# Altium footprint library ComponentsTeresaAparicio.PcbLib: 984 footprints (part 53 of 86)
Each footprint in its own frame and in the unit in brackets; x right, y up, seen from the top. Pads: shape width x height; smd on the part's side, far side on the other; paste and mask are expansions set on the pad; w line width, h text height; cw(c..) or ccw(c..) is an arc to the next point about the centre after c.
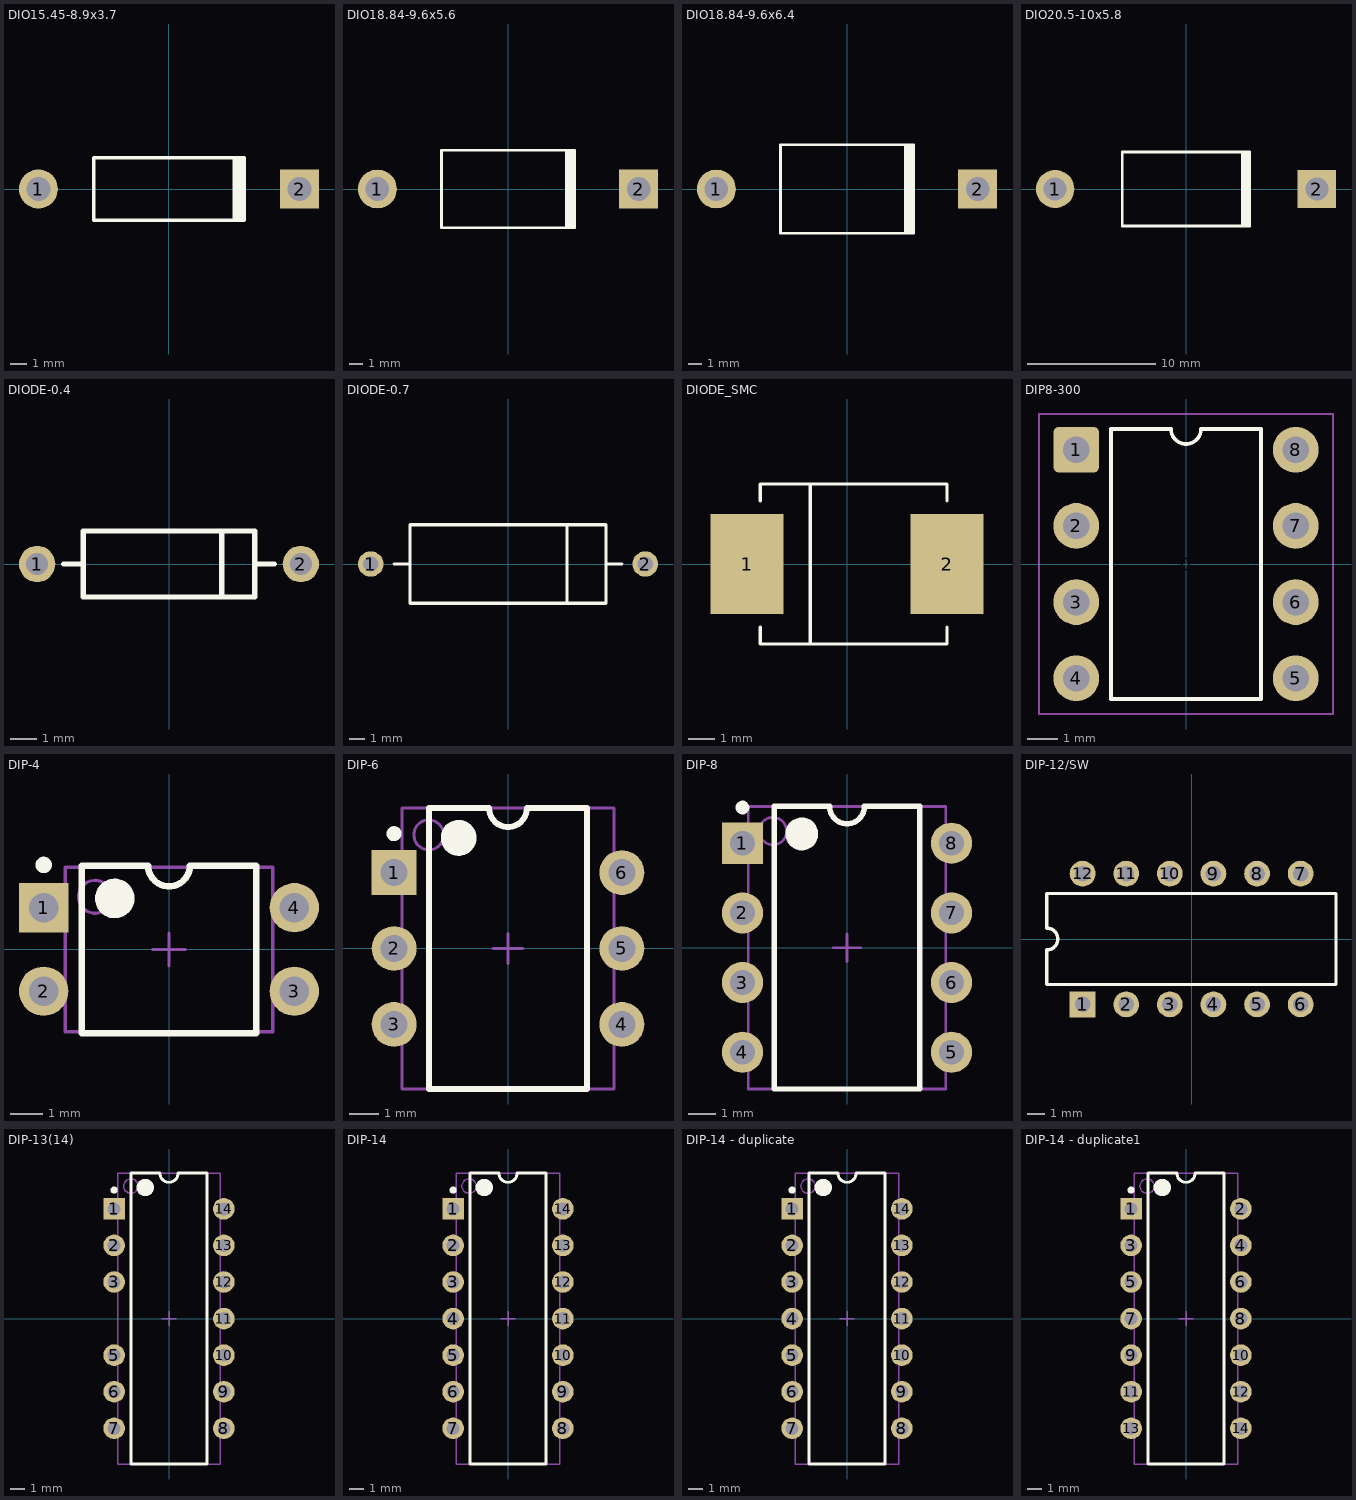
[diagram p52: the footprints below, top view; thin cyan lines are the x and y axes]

## DIO15.45-8.9x3.7 [mm] "Diode, Axial; Body 8.9 x 3.7 mm (LxDia. max), Lead Dia. 1.09 mm (max)"
height 3.7
pads (2):
  round 2.3 hole 1.4: 1(-7.725,0)
  rect 2.3x2.3 hole 1.4: 2(7.725,0)
Top Overlay:
  rectangle: 3.75,-1.85 4.55,1.85
  lines w0.2: 4.45,-1.85 -4.45,-1.85 -4.45,1.85 4.45,1.85

## DIO18.84-9.6x5.6 [mm] "Diode, Axial; Body 9.5 x 5.6 mm (LxDia. max), Lead Dia. 1.32 mm (max)"
height 5.6
pads (2):
  round 2.8 hole 1.7: 1(-9.42,0)
  rect 2.8x2.8 hole 1.7: 2(9.42,0)
Top Overlay:
  rectangle: 4.1,-2.8 4.9,2.8
  lines w0.2: 4.8,-2.8 -4.8,-2.8 -4.8,2.8 4.8,2.8

## DIO18.84-9.6x6.4 [mm] "Diode, Axial; Body 9.5 x 6.4 mm (LxDia. max), Lead Dia. 1.32 mm (max)"
height 6.4
pads (2):
  round 2.8 hole 1.7: 1(-9.42,0)
  rect 2.8x2.8 hole 1.7: 2(9.42,0)
Top Overlay:
  rectangle: 4.1,-3.2 4.9,3.2
  lines w0.2: 4.8,-3.2 -4.8,-3.2 -4.8,3.2 4.8,3.2

## DIO20.5-10x5.8 [mm] "Diode, Axial; Body 9.9 x 5.8 mm (LxDia. max), Lead Dia. 1.5 mm (max)"
height 5.8
pads (2):
  round 3 hole 1.8: 1(-10.25,0)
  rect 3x3 hole 1.8: 2(10.25,0)
Top Overlay:
  rectangle: 4.3,-2.9 5.1,2.9
  lines w0.2: 5,-2.9 -5,-2.9 -5,2.9 5,2.9

## DIODE-0.4 [mm] "Diode, Thru-Hole; 2 Leads; 0.4 in Pin Spacing"
height 2.54
pads (2):
  round 1.4 hole 0.85: 1(-5.08,0) 2(5.08,0)
Top Overlay:
  lines w0.2: -4.064,0 -3.302,0 ; 2.032,-1.27 2.032,1.27 ; 3.302,0 4.064,0 ; -3.302,-1.27 -3.302,1.27 3.302,1.27 3.302,-1.27 -3.302,-1.27

## DIODE-0.7 [mm] "Diode, Thru-Hole; 2 Leads; 0.7 in Pin Spacing"
height 5.08
pads (2):
  round 1.65 hole 1: 1(-8.89,0) 2(8.89,0)
Top Overlay:
  lines w0.2: -7.366,0 -6.35,0 ; 3.81,-2.54 3.81,2.54 ; 6.35,0 7.366,0 ; -6.35,-2.54 -6.35,2.54 6.35,2.54 6.35,-2.54 -6.35,-2.54

## DIODE_SMC [mil] "Diode; 2 Leads"
pads (2):
  rect 110x150 smd: 1(-150,0) 2(150,0)
Top Overlay:
  lines w5: -130,-95 -130,-120 150,-120 150,-95 ; -130,95 -130,120 150,120 150,95 ; -55,-120 -55,120
Mechanical 1:
  lines w1: -130,-120 150,-120 ; -130,120 150,120

## DIP8-300 [mil] "DIP, 8-Leads, 0.300\" lead span , 0.100\" lead pitch, IPC Density A"
height 210
pads (9):
  round 39.37 on Mech14: 0(0,0)
  rrect25% 60x60 hole 35: 1(-144,150)
  round 60 hole 35: 2(-144,50) 3(-144,-50) 4(-144,-150) 5(144,-150) 6(144,-50) 7(144,50) 8(144,150)
Top Overlay:
  lines w5: -98.43,-177.17 98.43,-177.17 98.43,177.17 19.69,177.17 cw(c0,177.17) -19.69,177.17 -98.43,177.17 -98.43,-177.17
Mechanical 13:
  lines w3: -98.43,-177.17 -98.43,177.17 -19.69,177.17 ccw(c0,177.17) 19.69,177.17 98.43,177.17 98.43,-177.17 -98.43,-177.17
Mechanical 14:
  lines w3: -192.91,-196.85 192.91,-196.85 192.91,196.85 -192.91,196.85 -192.91,-196.85
3D body: height 165, standoff -105, extent -149,-225 161,225

## DIP-4 [mm] "DIP; 4 Leads; Row Spacing 7.62 mm; Pitch 2.54 mm"
height 5.6
pads (4):
  rect 1.5x1.5 hole 0.9: 1(-3.81,1.27)
  round 1.5 hole 0.9: 2(-3.81,-1.27) 3(3.81,-1.27) 4(3.81,1.27)
Top Overlay:
  circle w0.25: c-3.81,2.57 r0.125
  circle w0.6: c-1.65,1.55 r0.3
  lines w0.2: -2.65,-2.55 -2.65,2.55 -0.635,2.55 ccw(c0,2.55) 0.635,2.55 2.65,2.55 2.65,-2.55 -2.65,-2.55
Mechanical 13:
  circle w0.1: c-2.25,1.6 r0.5
  lines w0.1: -3.15,-2.5 -3.15,2.5 3.15,2.5 3.15,-2.5 -3.15,-2.5
Mechanical 15:
  lines w0.1: -0.5,0 0.5,0 ; 0,-0.5 0,0.5
3D body: height 5.6, standoff 0, extent -3.15,-2.5 3.15,2.5

## DIP-6 [mm] "DIP; 6 Leads; Row Spacing 7.62 mm; Pitch 2.54 mm"
height 5.46
pads (6):
  rect 1.5x1.5 hole 0.9: 1(-3.81,2.54)
  round 1.5 hole 0.9: 2(-3.81,0) 3(-3.81,-2.54) 4(3.81,-2.54) 5(3.81,0) 6(3.81,2.54)
Top Overlay:
  circle w0.25: c-3.81,3.84 r0.125
  circle w0.6: c-1.65,3.7 r0.3
  lines w0.2: -2.65,-4.7 -2.65,4.7 -0.635,4.7 ccw(c0,4.7) 0.635,4.7 2.65,4.7 2.65,-4.7 -2.65,-4.7
Mechanical 13:
  circle w0.1: c-2.65,3.8 r0.5
  lines w0.1: -3.55,-4.7 -3.55,4.7 3.55,4.7 3.55,-4.7 -3.55,-4.7
Mechanical 15:
  lines w0.1: -0.5,0 0.5,0 ; 0,-0.5 0,0.5
3D body: height 5.46, standoff 0, extent -3.55,-4.7 3.55,4.7

## DIP-8 [mm] "DIP; 8 Leads; Row Spacing 7.62 mm; Pitch 2.54 mm"
height 5.08
pads (8):
  rect 1.5x1.5 hole 0.9: 1(-3.81,3.81)
  round 1.5 hole 0.9: 2(-3.81,1.27) 3(-3.81,-1.27) 4(-3.81,-3.81) 5(3.81,-3.81) 6(3.81,-1.27) 7(3.81,1.27) 8(3.81,3.81)
Top Overlay:
  circle w0.6: c-1.65,4.15 r0.3
  circle w0.25: c-3.81,5.11 r0.125
  lines w0.2: -2.65,-5.15 2.65,-5.15 2.65,5.15 0.635,5.15 cw(c0,5.15) -0.635,5.15 -2.65,5.15 -2.65,-5.15
Mechanical 13:
  circle w0.1: c-2.7,4.25 r0.5
  lines w0.1: -3.6,-5.15 3.6,-5.15 3.6,5.15 -3.6,5.15 -3.6,-5.15
Mechanical 15:
  lines w0.1: -0.5,0 0.5,0 ; 0,-0.5 0,0.5
3D body: height 5.08, standoff 0, extent -3.6,-5.15 3.6,5.15

## DIP-12/SW [mm] "DIP Switch; 12 Leads"
height 5.8
pads (12):
  rect 1.5x1.5 hole 0.9: 1(-6.35,-3.81)
  round 1.5 hole 0.9: 2(-3.81,-3.81) 3(-1.27,-3.81) 4(1.27,-3.81) 5(3.81,-3.81) 6(6.35,-3.81) 7(6.35,3.81) 8(3.81,3.81) 9(1.27,3.81) 10(-1.27,3.81) 11(-3.81,3.81) 12(-6.35,3.81)
Top Overlay:
  lines w0.2: -8.43,-2.65 8.41,-2.65 8.41,2.65 -8.43,2.65 -8.43,0.635 cw(c-8.43,0) -8.43,-0.635 -8.43,-2.65

## DIP-13(14) [mm] "DIP; 14 Leads (1 Absent); Row Spacing 7.62 mm; Pitch 2.54 mm"
height 5.33
pads (13):
  rect 1.5x1.5 hole 0.9: 1(-3.81,7.62)
  round 1.5 hole 0.9: 2(-3.81,5.08) 3(-3.81,2.54) 5(-3.81,-2.54) 6(-3.81,-5.08) 7(-3.81,-7.62) 8(3.81,-7.62) 9(3.81,-5.08) 10(3.81,-2.54) 11(3.81,0) 12(3.81,2.54) 13(3.81,5.08) 14(3.81,7.62)
Top Overlay:
  circle w0.25: c-3.81,8.92 r0.125
  circle w0.6: c-1.65,9.1 r0.3
  lines w0.2: -2.65,-10.1 -2.65,10.1 -0.635,10.1 ccw(c0,10.1) 0.635,10.1 2.65,10.1 2.65,-10.1 -2.65,-10.1
Mechanical 13:
  circle w0.1: c-2.65,9.2 r0.5
  lines w0.1: -3.55,-10.1 -3.55,10.1 3.55,10.1 3.55,-10.1 -3.55,-10.1
Mechanical 15:
  lines w0.1: -0.5,0 0.5,0 ; 0,-0.5 0,0.5
3D body: height 5.33, standoff 0, extent -3.55,-10.1 3.55,10.1

## DIP-14 [mm] "DIP; 14 Leads; Row Spacing 7.62 mm; Pitch 2.54 mm"
height 5.08
pads (14):
  rect 1.5x1.5 hole 0.9: 1(-3.81,7.62)
  round 1.5 hole 0.9: 2(-3.81,5.08) 3(-3.81,2.54) 4(-3.81,0) 5(-3.81,-2.54) 6(-3.81,-5.08) 7(-3.81,-7.62) 8(3.81,-7.62) 9(3.81,-5.08) 10(3.81,-2.54) 11(3.81,0) 12(3.81,2.54) 13(3.81,5.08) 14(3.81,7.62)
Top Overlay:
  circle w0.6: c-1.65,9.1 r0.3
  circle w0.25: c-3.81,8.92 r0.125
  lines w0.2: -2.65,-10.1 2.65,-10.1 2.65,10.1 0.635,10.1 cw(c0,10.1) -0.635,10.1 -2.65,10.1 -2.65,-10.1
Mechanical 13:
  circle w0.1: c-2.7,9.2 r0.5
  lines w0.1: -3.6,-10.1 3.6,-10.1 3.6,10.1 -3.6,10.1 -3.6,-10.1
Mechanical 15:
  lines w0.1: -0.5,0 0.5,0 ; 0,-0.5 0,0.5
3D body: height 5.08, standoff 0, extent -3.6,-10.1 3.6,10.1

## DIP-14 - duplicate [mm] "DIP; 14 Leads; Row Spacing 7.62 mm; Pitch 2.54 mm"
height 5.08
pads (14):
  rect 1.5x1.5 hole 0.9: 1(-3.81,7.62)
  round 1.5 hole 0.9: 2(-3.81,5.08) 3(-3.81,2.54) 4(-3.81,0) 5(-3.81,-2.54) 6(-3.81,-5.08) 7(-3.81,-7.62) 8(3.81,-7.62) 9(3.81,-5.08) 10(3.81,-2.54) 11(3.81,0) 12(3.81,2.54) 13(3.81,5.08) 14(3.81,7.62)
Top Overlay:
  circle w0.6: c-1.65,9.1 r0.3
  circle w0.25: c-3.81,8.92 r0.125
  lines w0.2: -2.65,-10.1 2.65,-10.1 2.65,10.1 0.635,10.1 cw(c0,10.1) -0.635,10.1 -2.65,10.1 -2.65,-10.1
Mechanical 13:
  circle w0.1: c-2.7,9.2 r0.5
  lines w0.1: -3.6,-10.1 3.6,-10.1 3.6,10.1 -3.6,10.1 -3.6,-10.1
Mechanical 15:
  lines w0.1: -0.5,0 0.5,0 ; 0,-0.5 0,0.5
3D body: height 5.08, standoff 0, extent -3.6,-10.1 3.6,10.1

## DIP-14 - duplicate1 [mm] "DIP; 14 Leads; Row Spacing 7.62 mm; Pitch 2.54 mm"
height 5.08
pads (14):
  rect 1.5x1.5 hole 0.9: 1(-3.81,7.62)
  round 1.5 hole 0.9: 2(3.81,7.62) 3(-3.81,5.08) 4(3.81,5.08) 5(-3.81,2.54) 6(3.81,2.54) 7(-3.81,0) 8(3.81,0) 9(-3.81,-2.54) 10(3.81,-2.54) 11(-3.81,-5.08) 12(3.81,-5.08) 13(-3.81,-7.62) 14(3.81,-7.62)
Top Overlay:
  circle w0.6: c-1.65,9.1 r0.3
  circle w0.25: c-3.81,8.92 r0.125
  lines w0.2: -2.65,-10.1 2.65,-10.1 2.65,10.1 0.635,10.1 cw(c0,10.1) -0.635,10.1 -2.65,10.1 -2.65,-10.1
Mechanical 13:
  circle w0.1: c-2.7,9.2 r0.5
  lines w0.1: -3.6,-10.1 3.6,-10.1 3.6,10.1 -3.6,10.1 -3.6,-10.1
Mechanical 15:
  lines w0.1: -0.5,0 0.5,0 ; 0,-0.5 0,0.5
3D body: height 4.19, standoff -2.67, extent -3.81,-9.652 4.064,9.398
